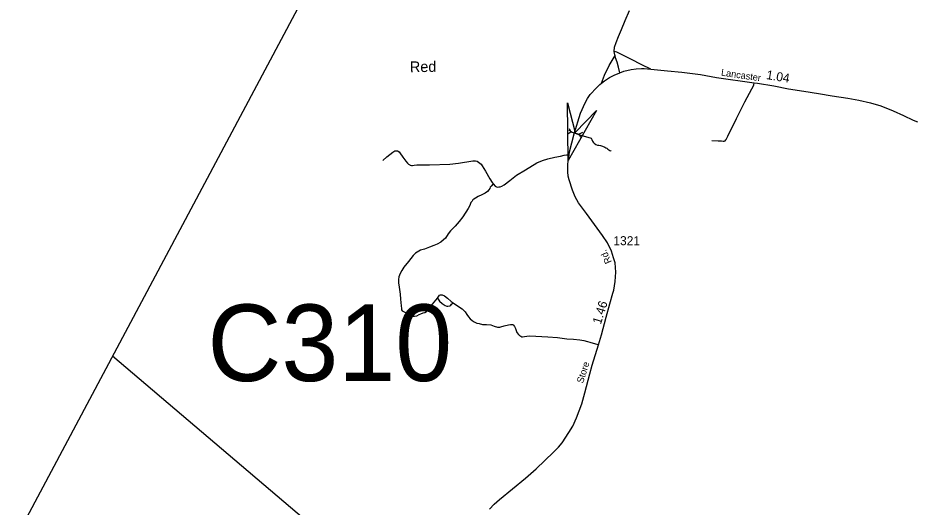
# Model space of a CAD drawing. Extents: x 2220236 to 2384410, y 720751 to 894131.
# Drawn here: x 2273739 to 2286237, y 858039 to 864850 of the extents above; entities that cross this region are included whole.
import ezdxf

# ---------------------------------------------------------------- set-up
doc = ezdxf.new("R2010")
doc.units = 0
doc.layers.add('Default', color=7, linetype='Continuous')

msp = doc.modelspace()

# ---------------------------------------------------------------- linework, layer by layer
at = {"layer": 'Default'}
for p, q in [((2281398, 863238), (2281442, 863264)), ((2281418, 863309), (2281442, 863264)), ((2281442, 863264), (2281558, 863231)), ((2281602, 863257), (2281558, 863231)), ((2281582, 863186), (2281558, 863231))]:
    msp.add_line(p, q, dxfattribs=at)
for points in [[(2293118, 894131), (2291904, 891776), (2258822, 829665), (2255410, 823324), (2242089, 797599), (2231460, 775981), (2225011, 762953), (2220576, 753519)], [(2282124, 864088), (2282106, 864167), (2282086, 864237), (2282066, 864297), (2282057, 864326), (2282054, 864338), (2282046, 864384), (2282052, 864444), (2282072, 864507), (2282107, 864590), (2282147, 864688), (2282199, 864814), (2282259, 864956)], [(2282555, 864136), (2282431, 864199), (2282276, 864278), (2282129, 864352), (2282083, 864372), (2282046, 864384)], [(2281869, 863941), (2281911, 864053), (2281974, 864188), (2282029, 864280), (2282057, 864326)], [(2280310, 858008), (2280374, 858081), (2280449, 858145), (2280812, 858441), (2280957, 858570), (2281199, 858804), (2281268, 858875), (2281321, 858935), (2281416, 859078), (2281469, 859166), (2281520, 859283), (2281595, 859478), (2281637, 859630), (2281708, 859893), (2281739, 860013), (2281828, 860299), (2281871, 860436), (2281934, 860686), (2281985, 860871), (2282027, 861019), (2282040, 861061), (2282060, 861182), (2282067, 861309), (2282058, 861442), (2282036, 861510), (2282006, 861602), (2281953, 861720), (2281884, 861819), (2281659, 862127), (2281550, 862275), (2281501, 862358), (2281466, 862451), (2281417, 862595), (2281404, 862649), (2281398, 862708), (2281398, 862765), (2281398, 862811), (2281406, 862858), (2281419, 862942), (2281425, 862986), (2281489, 863235), (2281576, 863526), (2281641, 863668), (2281672, 863727), (2281712, 863783), (2281797, 863878), (2281844, 863922), (2281869, 863941), (2281912, 863973), (2281981, 864019), (2282047, 864056), (2282124, 864088)], [(2282124, 864088), (2282178, 864111), (2282284, 864134), (2282350, 864141), (2282424, 864145), (2282462, 864146), (2282555, 864136), (2282788, 864113), (2282986, 864095), (2283250, 864061), (2283473, 864023), (2283995, 863948), (2284043, 863941), (2284269, 863903), (2284474, 863865), (2284686, 863829), (2284890, 863799), (2285080, 863765), (2285299, 863734), (2285452, 863705), (2285615, 863669), (2285761, 863628), (2285930, 863559), (2286076, 863490), (2286212, 863427), (2286273, 863403)], [(2283404, 863142), (2283493, 863139), (2283539, 863137), (2283562, 863135), (2283576, 863135), (2283590, 863139), (2283601, 863151), (2283606, 863160), (2283629, 863206), (2283748, 863448), (2283865, 863682), (2283964, 863864), (2283983, 863898), (2283990, 863921), (2283995, 863948)], [(2281415, 863291), (2281427, 863283), (2281439, 863274), (2281459, 863260), (2281500, 863248), (2281550, 863229), (2281580, 863220), (2281727, 863177), (2281736, 863160), (2281744, 863136), (2281753, 863121), (2281768, 863105), (2281789, 863089), (2281811, 863081), (2281832, 863078), (2281853, 863075), (2281884, 863065), (2281915, 863052), (2281931, 863042), (2281941, 863036), (2281956, 863025), (2281971, 863013), (2281985, 863004), (2281997, 862998), (2282003, 862997)], [(2278822, 862866), (2278879, 862917), (2278964, 862983), (2278989, 862998), (2279010, 863000), (2279027, 863000), (2279048, 862987), (2279061, 862974), (2279101, 862913), (2279143, 862858), (2279167, 862830), (2279181, 862813), (2279198, 862803), (2279205, 862801), (2279220, 862796), (2279237, 862796), (2279260, 862801), (2279294, 862805), (2279351, 862807), (2279471, 862807), (2279755, 862813), (2279876, 862830), (2280075, 862860), (2280115, 862860), (2280136, 862854), (2280155, 862843), (2280174, 862830), (2280193, 862813), (2280208, 862792), (2280254, 862718), (2280314, 862608), (2280347, 862561), (2280361, 862542)], [(2280361, 862542), (2280389, 862508), (2280406, 862500), (2280421, 862496), (2280438, 862498), (2280459, 862500), (2280478, 862508), (2280512, 862527), (2280594, 862587), (2280683, 862659), (2280810, 862737), (2280969, 862832), (2281045, 862866), (2281121, 862890), (2281218, 862911), (2281299, 862928), (2281349, 862940), (2281382, 862942), (2281419, 862942)], [(2280361, 862542), (2280330, 862510), (2280319, 862496), (2280313, 862477), (2280298, 862455), (2280281, 862436), (2280247, 862411), (2280203, 862388), (2280150, 862364), (2280114, 862343), (2280090, 862328), (2280076, 862316), (2280065, 862301), (2280050, 862280), (2280033, 862239), (2280010, 862197), (2279938, 862081), (2279887, 862015), (2279828, 861951), (2279767, 861886), (2279733, 861843), (2279697, 861786), (2279667, 861759), (2279629, 861729), (2279580, 861702), (2279532, 861680), (2279472, 861657), (2279403, 861632), (2279345, 861615), (2279322, 861604), (2279301, 861591), (2279278, 861574), (2279246, 861543), (2279180, 861458), (2279115, 861378), (2279086, 861335), (2279063, 861293), (2279046, 861246), (2279042, 861210), (2279040, 861162), (2279048, 861100), (2279063, 861003), (2279069, 860935), (2279071, 860888), (2279080, 860842), (2279084, 860804), (2279084, 860785), (2279090, 860772), (2279110, 860761), (2279129, 860755), (2279152, 860751), (2279181, 860732), (2279211, 860715), (2279241, 860698), (2279264, 860696), (2279294, 860700), (2279330, 860719), (2279353, 860732), (2279385, 860742), (2279406, 860751), (2279429, 860763), (2279467, 860810), (2279586, 860946)], [(2279586, 860946), (2279603, 860977), (2279613, 860988), (2279628, 860994), (2279647, 860994), (2279683, 860979), (2279725, 860950), (2279776, 860903), (2279802, 860882)], [(2279586, 860946), (2279611, 860907), (2279649, 860874), (2279689, 860846), (2279713, 860838), (2279727, 860835), (2279757, 860842), (2279768, 860852), (2279780, 860865), (2279802, 860882)], [(2279802, 860882), (2279865, 860842), (2279926, 860802), (2279952, 860778), (2279969, 860759), (2279992, 860723), (2280017, 860687), (2280039, 860660), (2280068, 860636), (2280096, 860619), (2280132, 860602), (2280166, 860594), (2280210, 860583), (2280267, 860581), (2280326, 860577), (2280375, 860558), (2280422, 860545), (2280451, 860543), (2280468, 860547), (2280513, 860562), (2280572, 860579), (2280599, 860581), (2280618, 860583), (2280632, 860580), (2280643, 860570), (2280659, 860554), (2280671, 860528), (2280690, 860471), (2280712, 860444), (2280726, 860429), (2280743, 860418), (2280760, 860412), (2280769, 860412), (2280796, 860414), (2280828, 860418), (2280866, 860422), (2280955, 860420), (2281122, 860412), (2281255, 860399), (2281387, 860384), (2281478, 860378), (2281567, 860367), (2281624, 860357), (2281672, 860344), (2281706, 860334), (2281751, 860323), (2281804, 860306), (2281828, 860299)], [(2275057, 860147), (2277630, 857957), (2278166, 857514), (2278960, 856846), (2279659, 856255), (2280036, 855932), (2280524, 855515), (2281255, 854906), (2282204, 854120), (2282204, 854118), (2282887, 853544), (2283435, 853085), (2284237, 852417), (2284916, 851850), (2285495, 851359), (2286093, 850859), (2286778, 850262)]]:
    msp.add_lwpolyline(points, dxfattribs=at)
msp.add_lwpolyline([(2281798, 863563), (2281403, 862867), (2281397, 863667), (2281504, 863254)], close=True, dxfattribs=at)

# ---------------------------------------------------------------- texts
for s, height, rotation, p in [('Red', 150, 0.9491, (2279201, 864094)), ('Lancaster', 95, 351.7715, (2283530, 864048)), ('1.04', 125, 350.4884, (2284158, 864001)), ('Rd.', 95, 114.8796, (2282013, 861453)), ('1.46', 125, 72.6768, (2281859, 860576)), ('Store', 95, 72.6892, (2281612, 859756))]:
    msp.add_text(s, height=height, rotation=rotation, dxfattribs=at).set_placement(p)
for s, height, p in [('1321', 125, (2282034, 861686)), ('C310', 1066.3, (2276380, 859794))]:
    msp.add_text(s, height=height, dxfattribs=at).set_placement(p)

doc.saveas('drawing.dxf')
